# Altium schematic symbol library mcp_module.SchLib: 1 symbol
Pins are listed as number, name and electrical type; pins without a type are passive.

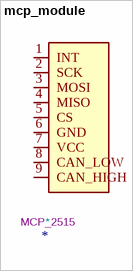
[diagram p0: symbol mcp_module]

## mcp_module
designator *  Reference: MCP_2515
pins: 1 INT, 2 SCK, 3 MOSI, 4 MISO, 5 CS, 6 GND, 7 VCC, 8 CAN_LOW, 9 CAN_HIGH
